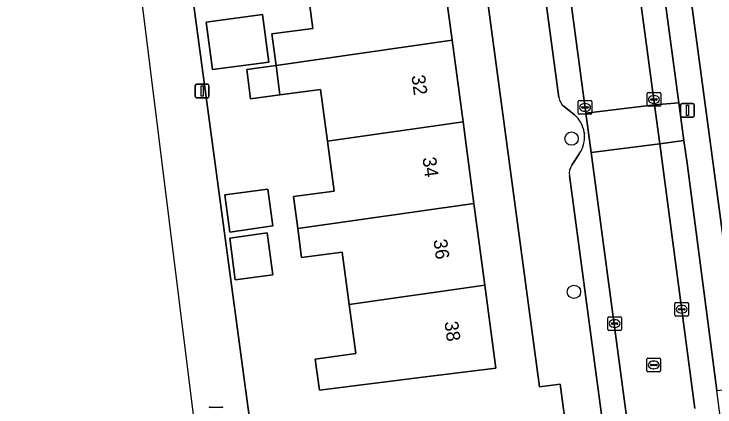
# Model space of a CAD drawing. Extents: x 163426 to 164192, y 380329 to 381641.
# Drawn here: x 163513 to 163564.3, y 381374.1 to 381402.9 of the extents above; entities that cross this region are included whole.
import ezdxf

# ---------------------------------------------------------------- set-up
doc = ezdxf.new("R2010")
doc.units = 0
for name, color, linetype in [('IMGEO_Boom', 7, 'Continuous'), ('IMGEO_Erf', 7, 'Continuous'), ('IMGEO_Kolk', 7, 'Continuous'), ('IMGEO_Lichtmast', 7, 'Continuous'), ('IMGEO_Pand', 7, 'Continuous'), ('IMGEO_Pand_nummerreeks', 7, 'Continuous'), ('IMGEO_Parkeervlak_open', 7, 'Continuous'), ('IMGEO_Rijbaan_lokaal_open', 7, 'Continuous'), ('IMGEO_Rioolput', 7, 'Continuous'), ('IMGEO_Voetpad_open', 7, 'Continuous')]:
    doc.layers.add(name, color=color, linetype=linetype)

msp = doc.modelspace()

# ---------------------------------------------------------------- linework, layer by layer
at = {"layer": 'IMGEO_Boom'}
for centre in [(163553.796, 381393.736), (163553.975, 381382.509)]:
    msp.add_circle(centre, 0.489, dxfattribs=at)
at = {"layer": 'IMGEO_Erf'}
for points in [[(163557.232, 381443.507), (163566.206, 381376.628), (163570.178, 381377.161), (163569.35, 381383.284), (163568.544, 381389.24), (163567.74, 381395.178), (163566.936, 381401.125), (163566.134, 381407.052), (163565.331, 381412.988), (163565.293, 381413.269), (163566.504, 381413.42), (163565.75, 381419.111), (163564.961, 381425.061), (163564.17, 381431.032), (163563.384, 381436.962), (163562.564, 381443.153)], [(163545.331, 381421.187), (163524.164, 381418.345), (163536.034, 381330.138), (163541.759, 381330.889)], [(163557.774, 381339.564), (163557.372, 381342.692), (163552.956, 381375.749), (163551.459, 381375.552), (163545.331, 381421.187)], [(163544.311, 381406.556), (163545.058, 381400.945), (163545.854, 381394.965), (163546.65, 381388.988), (163547.446, 381383.008), (163548.257, 381376.912), (163543.296, 381376.294), (163535.339, 381375.304), (163535.035, 381377.586), (163538.011, 381377.982), (163537.531, 381381.591), (163537.021, 381385.425), (163534.044, 381385.028), (163533.762, 381387.145), (163533.449, 381389.494), (163536.425, 381389.889), (163535.938, 381393.548), (163535.435, 381397.332), (163532.457, 381396.935), (163530.309, 381396.649), (163530.024, 381398.795), (163532.169, 381399.102), (163531.862, 381401.411), (163534.859, 381401.81), (163534.366, 381405.509)]]:
    msp.add_lwpolyline(points, dxfattribs=at)
for points in [[(163531.651, 381399.347), (163527.513, 381398.796), (163527.05, 381402.277), (163531.188, 381402.827)], [(163528.789, 381386.892), (163528.426, 381389.62), (163531.572, 381390.038), (163531.931, 381387.341)], [(163531.943, 381383.752), (163529.185, 381383.384), (163528.777, 381386.447), (163531.531, 381386.841)]]:
    msp.add_lwpolyline(points, close=True, dxfattribs=at)
at = {"layer": 'IMGEO_Kolk'}
for p, q in [((163559.326, 381396.179), (163559.326, 381397.031)), ((163559.401, 381397.105), (163560.253, 381397.105)), ((163559.814, 381396.885), (163559.839, 381396.885)), ((163560.327, 381397.031), (163560.327, 381396.179)), ((163554.286, 381395.597), (163554.286, 381396.449)), ((163554.361, 381396.523), (163555.213, 381396.523)), ((163554.774, 381396.303), (163554.799, 381396.303)), ((163555.287, 381396.449), (163555.287, 381395.597)), ((163559.585, 381396.599), (163559.585, 381396.611)), ((163560.023, 381396.562), (163559.625, 381396.562)), ((163559.628, 381396.648), (163560.026, 381396.648)), ((163559.837, 381396.325), (163559.812, 381396.325)), ((163560.069, 381396.611), (163560.069, 381396.599)), ((163554.545, 381396.017), (163554.545, 381396.029)), ((163554.983, 381395.98), (163554.585, 381395.98)), ((163554.588, 381396.066), (163554.986, 381396.066)), ((163555.029, 381396.029), (163555.029, 381396.017)), ((163560.253, 381396.105), (163559.401, 381396.105)), ((163555.213, 381395.523), (163554.361, 381395.523)), ((163554.797, 381395.743), (163554.772, 381395.743)), ((163561.357, 381380.805), (163561.357, 381381.657)), ((163561.432, 381381.731), (163562.284, 381381.731)), ((163561.845, 381381.511), (163561.87, 381381.511)), ((163562.358, 381381.657), (163562.358, 381380.805)), ((163561.616, 381381.225), (163561.616, 381381.237)), ((163562.054, 381381.188), (163561.656, 381381.188)), ((163561.659, 381381.274), (163562.057, 381381.274)), ((163561.868, 381380.951), (163561.843, 381380.951)), ((163562.1, 381381.237), (163562.1, 381381.225)), ((163556.452, 381379.758), (163556.452, 381380.61)), ((163556.527, 381380.684), (163557.379, 381380.684)), ((163556.94, 381380.464), (163556.965, 381380.464)), ((163557.453, 381380.61), (163557.453, 381379.758)), ((163562.284, 381380.731), (163561.432, 381380.731)), ((163556.711, 381380.178), (163556.711, 381380.19)), ((163557.149, 381380.141), (163556.751, 381380.141)), ((163556.754, 381380.227), (163557.152, 381380.227)), ((163556.963, 381379.904), (163556.938, 381379.904)), ((163557.195, 381380.19), (163557.195, 381380.178)), ((163557.379, 381379.684), (163556.527, 381379.684)), ((163527.351, 381374.07), (163528.203, 381374.07))]:
    msp.add_line(p, q, dxfattribs=at)
for points in [[(163559.326, 381396.179), (163559.326, 381397.031)], [(163559.401, 381397.105), (163560.253, 381397.105)], [(163560.327, 381397.031), (163560.327, 381396.179)], [(163554.286, 381395.597), (163554.286, 381396.449)], [(163554.361, 381396.523), (163555.213, 381396.523)], [(163555.287, 381396.449), (163555.287, 381395.597)], [(163560.253, 381396.105), (163559.401, 381396.105)], [(163555.213, 381395.523), (163554.361, 381395.523)], [(163561.357, 381380.805), (163561.357, 381381.657)], [(163561.432, 381381.731), (163562.284, 381381.731)], [(163562.358, 381381.657), (163562.358, 381380.805)], [(163556.452, 381379.758), (163556.452, 381380.61)], [(163556.527, 381380.684), (163557.379, 381380.684)], [(163557.453, 381380.61), (163557.453, 381379.758)], [(163562.284, 381380.731), (163561.432, 381380.731)], [(163557.379, 381379.684), (163556.527, 381379.684)], [(163527.351, 381374.07), (163528.203, 381374.07)]]:
    msp.add_lwpolyline(points, dxfattribs=at)
for centre, radius, start, end in [((163559.403, 381397.029), 0.0765, 91.552, 178.448), ((163559.403, 381397.029), 0.0765, 91.552, 178.448), ((163560.251, 381397.029), 0.0765, 1.552, 88.448), ((163560.251, 381397.029), 0.0765, 1.552, 88.448), ((163554.363, 381396.447), 0.0765, 91.552, 178.448), ((163554.363, 381396.447), 0.0765, 91.552, 178.448), ((163555.211, 381396.447), 0.0765, 1.552, 88.448), ((163555.211, 381396.447), 0.0765, 1.552, 88.448), ((163559.625, 381396.608), 0.0403, 85.8775, 175.7526), ((163559.622, 381396.598), 0.0366, 178.938, 274.7102), ((163560.026, 381396.605), 0.043, 264.8664, 352.4533), ((163560.03, 381396.61), 0.0386, 1.7309, 96.639), ((163554.585, 381396.026), 0.0403, 85.8775, 175.7526), ((163554.582, 381396.016), 0.0366, 178.938, 274.7102), ((163554.986, 381396.023), 0.043, 264.8664, 352.4533), ((163554.99, 381396.028), 0.0386, 1.7309, 96.639), ((163559.403, 381396.181), 0.0765, 181.552, 268.448), ((163559.403, 381396.181), 0.0765, 181.552, 268.448), ((163560.251, 381396.181), 0.0765, 271.552, 358.448), ((163560.251, 381396.181), 0.0765, 271.552, 358.448), ((163554.363, 381395.599), 0.0765, 181.552, 268.448), ((163554.363, 381395.599), 0.0765, 181.552, 268.448), ((163555.211, 381395.599), 0.0765, 271.552, 358.448), ((163555.211, 381395.599), 0.0765, 271.552, 358.448), ((163561.434, 381381.655), 0.0765, 91.552, 178.448), ((163561.434, 381381.655), 0.0765, 91.552, 178.448), ((163562.282, 381381.655), 0.0765, 1.552, 88.448), ((163562.282, 381381.655), 0.0765, 1.552, 88.448), ((163561.656, 381381.234), 0.0403, 85.8775, 175.7526), ((163561.653, 381381.224), 0.0366, 178.938, 274.7102), ((163562.057, 381381.231), 0.043, 264.8664, 352.4533), ((163562.061, 381381.236), 0.0386, 1.7309, 96.639), ((163556.529, 381380.608), 0.0765, 91.552, 178.448), ((163556.529, 381380.608), 0.0765, 91.552, 178.448), ((163557.377, 381380.608), 0.0765, 1.552, 88.448), ((163557.377, 381380.608), 0.0765, 1.552, 88.448), ((163561.434, 381380.807), 0.0765, 181.552, 268.448), ((163561.434, 381380.807), 0.0765, 181.552, 268.448), ((163562.282, 381380.807), 0.0765, 271.552, 358.448), ((163562.282, 381380.807), 0.0765, 271.552, 358.448), ((163556.751, 381380.187), 0.0403, 85.8775, 175.7526), ((163556.748, 381380.177), 0.0366, 178.938, 274.7102), ((163557.152, 381380.184), 0.043, 264.8664, 352.4533), ((163557.156, 381380.189), 0.0386, 1.7309, 96.639), ((163556.529, 381379.76), 0.0765, 181.552, 268.448), ((163556.529, 381379.76), 0.0765, 181.552, 268.448), ((163557.377, 381379.76), 0.0765, 271.552, 358.448), ((163557.377, 381379.76), 0.0765, 271.552, 358.448), ((163527.353, 381373.994), 0.0765, 91.552, 178.448), ((163527.353, 381373.994), 0.0765, 91.552, 178.448), ((163528.201, 381373.994), 0.0765, 1.552, 88.448), ((163528.201, 381373.994), 0.0765, 1.552, 88.448)]:
    msp.add_arc(centre, radius, start, end, dxfattribs=at)
for centre, major_axis, ratio, start_param, end_param in [((163559.813, 381396.605), (-0.387, 0.002), 0.722429, 4.712389, 7.853982), ((163559.838, 381396.605), (-0.39, 0.002), 0.717154, 1.570796, 4.712389), ((163554.773, 381396.023), (-0.387, 0.002), 0.722429, 4.712389, 7.853982), ((163554.798, 381396.023), (-0.39, 0.002), 0.717154, 1.570796, 4.712389), ((163561.844, 381381.231), (-0.387, 0.002), 0.722429, 4.712389, 7.853982), ((163561.869, 381381.231), (-0.39, 0.002), 0.717154, 1.570796, 4.712389), ((163556.939, 381380.184), (-0.387, 0.002), 0.722429, 4.712389, 7.853982), ((163556.964, 381380.184), (-0.39, 0.002), 0.717154, 1.570796, 4.712389)]:
    msp.add_ellipse(centre, major_axis=major_axis, ratio=ratio, start_param=start_param, end_param=end_param, dxfattribs=at)
at = {"layer": 'IMGEO_Lichtmast'}
for p, q in [((163526.26, 381396.824), (163526.26, 381397.624)), ((163526.26, 381397.624), (163526.26, 381396.824)), ((163526.36, 381397.724), (163527.15, 381397.724)), ((163527.15, 381397.724), (163526.36, 381397.724)), ((163527.25, 381397.624), (163527.25, 381396.824)), ((163527.25, 381396.824), (163527.25, 381397.624)), ((163527.15, 381396.724), (163526.36, 381396.724)), ((163526.36, 381396.724), (163527.15, 381396.724)), ((163561.882, 381396.306), (163562.672, 381396.306)), ((163562.672, 381396.306), (163561.882, 381396.306)), ((163561.782, 381395.406), (163561.782, 381396.206)), ((163561.782, 381396.206), (163561.782, 381395.406)), ((163562.772, 381396.206), (163562.772, 381395.406)), ((163562.772, 381395.406), (163562.772, 381396.206)), ((163562.672, 381395.306), (163561.882, 381395.306)), ((163561.882, 381395.306), (163562.672, 381395.306))]:
    msp.add_line(p, q, dxfattribs=at)
for points in [[(163526.68, 381397.599), (163526.83, 381397.599), (163526.83, 381396.849), (163526.68, 381396.849), (163526.68, 381397.599)], [(163562.202, 381396.181), (163562.352, 381396.181), (163562.352, 381395.431), (163562.202, 381395.431), (163562.202, 381396.181)]]:
    msp.add_lwpolyline(points, dxfattribs=at)
for centre, start, end in [((163526.36, 381397.624), 90, 180), ((163526.36, 381397.624), 90, 180), ((163527.15, 381397.624), 0, 90), ((163527.15, 381397.624), 360, 90), ((163526.36, 381396.824), 180, 270), ((163526.36, 381396.824), 180, 270), ((163527.15, 381396.824), 270, 0), ((163527.15, 381396.824), 270, 0), ((163561.882, 381396.206), 90, 180), ((163561.882, 381396.206), 90, 180), ((163562.672, 381396.206), 0, 90), ((163562.672, 381396.206), 360, 90), ((163561.882, 381395.406), 180, 270), ((163561.882, 381395.406), 180, 270), ((163562.672, 381395.406), 270, 0), ((163562.672, 381395.406), 270, 0)]:
    msp.add_arc(centre, 0.1, start, end, dxfattribs=at)
at = {"layer": 'IMGEO_Pand'}
for points in [[(163544.311, 381406.556), (163544.617, 381406.599), (163544.565, 381406.967), (163534.366, 381405.509), (163534.859, 381401.81), (163531.862, 381401.411), (163532.169, 381399.102), (163545.058, 381400.945)], [(163527.05, 381402.277), (163527.513, 381398.796), (163531.651, 381399.347), (163531.188, 381402.827)], [(163532.169, 381399.102), (163532.457, 381396.935), (163535.435, 381397.332), (163535.938, 381393.548), (163545.854, 381394.965), (163545.058, 381400.945)], [(163532.169, 381399.102), (163530.024, 381398.795), (163530.309, 381396.649), (163532.457, 381396.935)], [(163533.762, 381387.145), (163546.65, 381388.988), (163545.854, 381394.965), (163535.938, 381393.548), (163536.425, 381389.889), (163533.449, 381389.494)], [(163528.426, 381389.62), (163528.789, 381386.892), (163531.931, 381387.341), (163531.572, 381390.038)], [(163533.762, 381387.145), (163534.044, 381385.028), (163537.021, 381385.425), (163537.531, 381381.591), (163547.446, 381383.008), (163546.65, 381388.988)], [(163528.777, 381386.447), (163529.185, 381383.384), (163531.943, 381383.752), (163531.531, 381386.841)], [(163537.531, 381381.591), (163538.011, 381377.982), (163535.035, 381377.586), (163535.339, 381375.304), (163543.296, 381376.294), (163548.257, 381376.912), (163547.446, 381383.008)]]:
    msp.add_lwpolyline(points, close=True, dxfattribs=at)
at = {"layer": 'IMGEO_Parkeervlak_open'}
for points in [[(163553.981, 381440.08), (163559.875, 381396.219), (163561.653, 381396.349), (163560.78, 381402.884), (163556.254, 381436.65), (163556.126, 381437.657)], [(163558.199, 381370.458), (163555.236, 381392.72), (163554.854, 381395.594), (163548.986, 381439.398)], [(163547.531, 381436.443), (163552.878, 381396.758)], [(163553.257, 381396.084), (163554.008, 381395.477)], [(163554.723, 381394.19), (163554.736, 381394.088)], [(163564.922, 381371.509), (163564.429, 381375.276), (163562.248, 381391.937), (163562.017, 381393.59), (163560.258, 381393.349), (163562.814, 381373.95)], [(163554.343, 381392.61), (163553.808, 381391.781)], [(163553.641, 381391.034), (163556.573, 381369.159)]]:
    msp.add_lwpolyline(points, dxfattribs=at)
msp.add_lwpolyline([(163559.875, 381396.219), (163560.258, 381393.349), (163562.017, 381393.59), (163561.653, 381396.349)], close=True, dxfattribs=at)
for centre, radius, start, end in [((163553.917, 381396.899), 1.049, 187.7173, 230.9821), ((163552.614, 381393.86), 2.135, 8.8843, 49.2249), ((163552.606, 381393.863), 2.142, 324.1904, 6.0288), ((163554.741, 381391.18), 1.11, 147.2304, 187.5658)]:
    msp.add_arc(centre, radius, start, end, dxfattribs=at)
at = {"layer": 'IMGEO_Rijbaan_lokaal_open'}
for points in [[(163531.559, 381329.55), (163531.559, 381329.55), (163536.034, 381330.138), (163524.164, 381418.345), (163523.981, 381419.703), (163513.264, 381499.338), (163513.175, 381500), (163513.136, 381500.288), (163511.008, 381500), (163500, 381498.51), (163468.966, 381494.225), (163468.645, 381494.168), (163468.815, 381492.913), (163468.816, 381492.902), (163510.586, 381498.135)], [(163553.981, 381440.08), (163553.761, 381441.842), (163553.557, 381443.21), (163553.536, 381443.371), (163553.162, 381446.201), (163548.151, 381445.563), (163548.736, 381441.267), (163548.986, 381439.398), (163554.854, 381395.594), (163559.875, 381396.219)], [(163554.854, 381395.594), (163555.236, 381392.72), (163560.258, 381393.349), (163559.875, 381396.219)]]:
    msp.add_lwpolyline(points, close=True, dxfattribs=at)
msp.add_lwpolyline([(163562.814, 381373.95), (163560.258, 381393.349), (163555.236, 381392.72), (163558.199, 381370.458)], dxfattribs=at)
at = {"layer": 'IMGEO_Rioolput'}
for p, q in [((163559.314, 381376.725), (163559.314, 381377.577)), ((163559.389, 381377.651), (163560.241, 381377.651)), ((163559.802, 381377.431), (163559.827, 381377.431)), ((163560.315, 381377.577), (163560.315, 381376.725)), ((163559.573, 381377.145), (163559.573, 381377.157)), ((163560.011, 381377.108), (163559.613, 381377.108)), ((163559.616, 381377.194), (163560.014, 381377.194)), ((163559.825, 381376.871), (163559.8, 381376.871)), ((163560.057, 381377.157), (163560.057, 381377.145)), ((163560.241, 381376.651), (163559.389, 381376.651))]:
    msp.add_line(p, q, dxfattribs=at)
for points in [[(163559.314, 381376.725), (163559.314, 381377.577)], [(163559.389, 381377.651), (163560.241, 381377.651)], [(163560.315, 381377.577), (163560.315, 381376.725)], [(163560.241, 381376.651), (163559.389, 381376.651)]]:
    msp.add_lwpolyline(points, dxfattribs=at)
for centre, radius, start, end in [((163559.391, 381377.575), 0.0765, 91.552, 178.448), ((163559.391, 381377.575), 0.0765, 91.552, 178.448), ((163560.239, 381377.575), 0.0765, 1.552, 88.448), ((163560.239, 381377.575), 0.0765, 1.552, 88.448), ((163559.613, 381377.154), 0.0403, 85.8775, 175.7526), ((163559.61, 381377.144), 0.0366, 178.938, 274.7102), ((163560.014, 381377.151), 0.043, 264.8664, 352.4533), ((163560.018, 381377.156), 0.0386, 1.7309, 96.639), ((163559.391, 381376.727), 0.0765, 181.552, 268.448), ((163559.391, 381376.727), 0.0765, 181.552, 268.448), ((163560.239, 381376.727), 0.0765, 271.552, 358.448), ((163560.239, 381376.727), 0.0765, 271.552, 358.448)]:
    msp.add_arc(centre, radius, start, end, dxfattribs=at)
for centre, major_axis, ratio, start_param, end_param in [((163559.801, 381377.151), (-0.387, 0.002), 0.722429, 4.712389, 7.853982), ((163559.826, 381377.151), (-0.39, 0.002), 0.717154, 1.570796, 4.712389)]:
    msp.add_ellipse(centre, major_axis=major_axis, ratio=ratio, start_param=start_param, end_param=end_param, dxfattribs=at)
at = {"layer": 'IMGEO_Voetpad_open'}
for points in [[(163538.748, 381515.131), (163537.994, 381521.009), (163537.691, 381522.857), (163537.726, 381523.034), (163537.586, 381523.962), (163537.28, 381526.001), (163532.089, 381524.073), (163534.881, 381503.195), (163535.005, 381502.264), (163535.961, 381502.355), (163536.277, 381500), (163541.312, 381462.422), (163539.823, 381462.212), (163545.149, 381422.545), (163545.331, 381421.187), (163551.459, 381375.552), (163552.956, 381375.749), (163557.372, 381342.692), (163557.774, 381339.564)], [(163571.177, 381345.417), (163569.239, 381353.811), (163569.01, 381355.444), (163568.044, 381362.93), (163566.405, 381375.146), (163566.206, 381376.628), (163557.232, 381443.507), (163556.995, 381445.271), (163550.532, 381493.434), (163549.67, 381494.227), (163548.887, 381500), (163545.916, 381521.903)], [(163556.126, 381437.657), (163556.254, 381436.65), (163560.78, 381402.884), (163561.653, 381396.349), (163562.017, 381393.59), (163562.248, 381391.937), (163564.429, 381375.276), (163564.875, 381375.333), (163565.356, 381371.575), (163564.922, 381371.509)], [(163552.878, 381396.758), (163547.531, 381436.443)], [(163554.008, 381395.477), (163553.257, 381396.084)], [(163554.736, 381394.088), (163554.723, 381394.19)], [(163553.808, 381391.781), (163554.343, 381392.61)], [(163556.573, 381369.159), (163553.641, 381391.034)]]:
    msp.add_lwpolyline(points, dxfattribs=at)
for centre, radius, start, end in [((163553.917, 381396.899), 1.049, 187.7173, 230.9821), ((163552.614, 381393.86), 2.135, 8.8843, 49.2249), ((163552.606, 381393.863), 2.142, 324.1904, 6.0288), ((163554.741, 381391.18), 1.11, 147.2304, 187.5658)]:
    msp.add_arc(centre, radius, start, end, dxfattribs=at)

# ---------------------------------------------------------------- texts
at = {"layer": 'IMGEO_Pand_nummerreeks'}
for s, p in [('32', (163542.076, 381398.34)), ('34', (163542.882, 381392.325)), ('36', (163543.687, 381386.313)), ('38', (163544.494, 381380.298))]:
    msp.add_text(s, height=1, rotation=277.6316, dxfattribs=at).set_placement(p)

doc.saveas('drawing.dxf')
